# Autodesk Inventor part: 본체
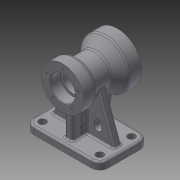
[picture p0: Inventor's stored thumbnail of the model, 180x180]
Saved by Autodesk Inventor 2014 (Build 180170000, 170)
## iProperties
Created: 2015-08
Part Number: 본체
Material: 일반
Document SubType Name: Modeling
Designer: USER
Density: 1 g/cm^3
Appearance: 기본값
Author: USER
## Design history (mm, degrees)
sketch "스케치1"
  geometry: L1 (-61, 40)-(61, 40); L2 (61, 40)-(61, -40); L3 (61, -40)-(-61, -40); L4 (-61, -40)-(-61, 40); L5 (-61, 40)-(61, -40); 2 further points
  constraints: 10 end point, 2 coincident, 2 parallel, 1 horizontal, 1 midpoint, 1 perpendicular
  dimensions: "d0" = 122 distance of L1.start L1.end; "d1" = 80 distance of L1.end L2.end
extrude "돌출1" new body sketch "스케치1" distance "d2" = 12; taper "d3" = 0 deg
sketch "스케치2"
  geometry: L1 (50, 90)-(-40, 90); L2 (50, 90)-(50, 130); L3 (50, 130)-(30, 130); L4 (30, 130)-(13.315, 116); L5 (13.315, 116)-(-14.804, 116); L6 (-14.804, 116)-(-20, 125); L7 (-20, 125)-(-40, 125); L8 (-40, 125)-(-40, 90); 2 further points
  constraints: 16 end point, 3 parallel, 2 perpendicular, 1 horizontal, 1 vertical alignment
  dimensions: "d4" = 90 distance of L1.start L1.end; "d5" = 90 distance from line of point (0, 0) L1; "d6" = 80 diameter of L3 L1; "d7" = 52 diameter of L5 L1; "d8" = 70 diameter of L7 L1; "d9" = 20 distance from line of L6.end L8; "d10" = 20 distance from line of L3.end L2; "d11" = 60 deg angle of L6 L5; "d12" = 40 deg angle of L4 L5
revolve "회전1" sketch "스케치2" stored, may be unused: angle "d13" = 90 deg
sketch "스케치3"
  geometry: C1 r 35 at (0, 0) reference; C2 r 20 at (0, 0); 1 further point
  constraints: 1 centre point, 1 coincident
  dimensions: "d14" = 40 diameter of C2
extrude "돌출2" cut sketch "스케치3" distance "d15" = 17; taper "d16" = 0 deg
sketch "스케치4"
  geometry: C1 r 40 at (0, 0) reference; C2 r 26 at (0, 0); 1 further point
  constraints: 1 centre point, 1 coincident
  dimensions: "d17" = 52 diameter of C2
extrude "돌출3" cut sketch "스케치4" distance "d18" = 20; taper "d19" = 0 deg
sketch "스케치5"
  geometry: C1 r 26 at (0, 0) reference; C2 r 19 at (0, 0); 1 further point
  constraints: 1 centre point, 1 coincident
  dimensions: "d20" = 38 diameter of C2
extrude "돌출4" cut sketch "스케치5" distance "d21" = 3; taper "d22" = 0 deg
sketch "스케치6"
  geometry: C1 r 20 at (0, 0) reference; C2 r 16 at (0, 0); 1 further point
  constraints: 1 centre point, 1 coincident
  dimensions: "d23" = 32 diameter of C2
extrude "돌출5" cut sketch "스케치6" stored distance "d24" = 3; taper "d25" = 0 deg
sketch "스케치7"
  geometry: L1 (61, 12)-(-61, 12) reference; L2 (-51, 12)-(-25.091, 83.185); L3 (51, 12)-(25.091, 83.185); L4 (61, 0)-(61, 12) reference; L5 (-61, 0)-(-61, 12) reference; A1 r 26 centre (0, 90) between (-25.091, 83.185) and (25.091, 83.185) reference; 1 further point
  constraints: 4 end point, 2 point on circle, 2 point on line
  dimensions: "d26" = 10 distance from line of L4 L3.start; "d27" = 10 distance from line of L5 L2.start; "d28" = 70 deg angle of L1 L2; "d29" = 70 deg angle of L1 L3
extrude "돌출6" join sketch "스케치7" stored distance "d30" = 12; taper "d31" = 0 deg
sketch "스케치8"
  geometry: L1 (40, 12)-(-40, 12) reference; L2 (-40, 55)-(-20, 55) reference; L3 (-20, 55)-(-14.804, 64) reference; L4 (-14.804, 64)-(13.315, 64) reference; L5 (13.315, 64)-(30, 50) reference; L6 (30, 50)-(50, 50) reference; L7 (-30, 12)-(-30, 55); L8 (30, 12)-(36.7, 50); L9 (-40, 0)-(-40, 12) reference; L10 (40, 0)-(40, 12) reference; 1 further point
  constraints: 4 end point, 3 point on line, 1 midpoint, 1 perpendicular
  dimensions: "d32" = 10 distance between parallel lines of L9 L7; "d33" = 10 distance from line of L10 L8.start; "d34" = 80 deg angle of L1 L8
feature "리브1" dims "d35" = 1, "d36" = 6, "d37" = 0, "d38" = 0, "d39" = 1, "d40" = 1
feature "리브2" dims "d41" = 1, "d42" = 6, "d43" = 0, "d44" = 0, "d45" = 1, "d46" = 1
feature "리브3" dims "d47" = 1, "d48" = 6, "d49" = 0, "d50" = 0, "d51" = 1, "d52" = 1
feature "리브4" dims "d53" = 1, "d54" = 6, "d55" = 0, "d56" = 0, "d57" = 1, "d58" = 1
sketch "스케치9"
  geometry: L1 (6, 64.702)-(6, 12) reference; L2 (51, 12)-(6, 12) reference; L3 (24, 30)-(24, 36); L4 (18, 30)-(18, 36); L5 (30, 36)-(30, 30); L6 (61, 0)-(61, 12) reference; A1 r 6 centre (24, 30) between (18, 30) and (30, 30); A2 r 6 centre (24, 36) between (30, 36) and (18, 36); 2 further points
  constraints: 8 end point, 4 point on circle, 4 tangent, 2 centre point, 2 parallel, 1 midpoint
  dimensions: "d59" = 12 distance between parallel lines of L4 L5; "d60" = 18 dimension on A1 A2; "d61" = 37 distance from line of L6 point (24, 33); "d62" = 18 distance from line of L3.start L2
extrude "돌출7" cut sketch "스케치9" distance "d63" = 12; taper "d64" = 0 deg
sketch "스케치10"
  geometry: L1 (61, 40)-(-61, 40) reference; L2 (-61, 40)-(-61, -40) reference; C1 r 6 at (-47, 26); C2 r 6 at (-47, -26); C3 r 6 at (47, -26); C4 r 6 at (47, 26); 1 further point
  constraints: 4 centre point, 2 horizontal alignment, 2 vertical alignment
  dimensions: "d65" = 12 diameter of C1; "d66" = 12 diameter of C2; "d67" = 12 diameter of C3; "d68" = 12 diameter of C4; "d69" = 94 distance of C4.centre C1.centre; "d70" = 52 distance of C3.centre C4.centre; "d71" = 14 distance from line of L2 C1.centre; "d72" = 14 distance from line of L1 C4.centre
extrude "돌출8" cut sketch "스케치10" distance "d73" = 12; taper "d74" = 0 deg
sketch "스케치11" dims "d75" = 54
  geometry: C1 r 20 at (0, 0) reference; C2 r 35 at (0, 0) reference; 3 further points
  constraints: 2 vertical alignment, 1 coincident, 2 other
hole "구멍1" sketch "스케치11" at (0, 27) diameter "d76" = 3.242; stored, may be unused: countersink angle "d80" = 90 deg, drill point angle "d82" = 118 deg; dims "d77" = 10, "d78" = 4, "d79" = 2, "d81" = 13
sketch "스케치12" dims "d86" = 66
  geometry: C1 r 26 at (0, 0) reference; 3 further points
  constraints: 2 vertical alignment, 1 coincident, 2 other
hole "구멍2" sketch "스케치12" at (0, -33) diameter "d87" = 3.242; stored, may be unused: countersink angle "d91" = 90 deg, drill point angle "d93" = 118 deg; dims "d88" = 10, "d89" = 4, "d90" = 2, "d92" = 13
chamfer "모따기1" distance "d97" = 1; stored, may be unused: second distance "d98" = 2, angle "d99" = 45 deg
fillet "모깎기1" dims "d100" = 3
fillet "모깎기2" dims "d101" = 3
fillet "모깎기3" dims "d102" = 14
fillet "모깎기4" dims "d103" = 3
fillet "모깎기5" dims "d104" = 3
fillet "모깎기6" dims "d105" = 5
fillet "모깎기7" dims "d106" = 0.3
fillet "모깎기8" dims "d107" = 3
sketch "스케치13"
  geometry: L1 (3, 53)-(3, 1) reference; L2 (-37.119, -3)-(0, -3) reference; 2 further points
  constraints: 1 other
  dimensions: "d108" = 24 distance from line of L1 point (-21, 13); "d109" = 16 distance from line of point (-21, 13) L2
feature "엠보싱1" sketch "스케치13" dims "d0" = 122, "d1" = 80, "d110" = 0.5, "d111" = 0
node "솔리드1"
mirror "대칭1"
pattern_circular "원형 패턴1" dims angle "d84" = 360 deg
pattern_circular "원형 패턴2" dims angle "d95" = 360 deg
